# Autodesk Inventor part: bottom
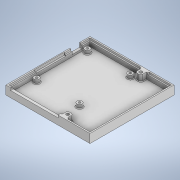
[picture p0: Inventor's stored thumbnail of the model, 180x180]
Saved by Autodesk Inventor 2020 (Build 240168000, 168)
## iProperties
Created: 2019-04
Part Number: bottom
Material: Generic
Document SubType Name: Modeling
Designer: Eli
Density: 1 g/cm^3
Appearance: Default
Author: Eli
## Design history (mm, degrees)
node "Blocks"
  sketch "raspberry pi"
    geometry: L1 (2.215, -51.877)-(7.411, -51.877); L2 (7.411, -51.877)-(7.411, -54.533); L3 (7.411, -54.533)-(2.215, -54.533); L4 (2.215, -54.533)-(2.215, -51.877); L5 (0, -50.5)-(-2.6, -50.5); L6 (-2.6, -50.5)-(-2.6, -56.5); L7 (-2.6, -56.5)-(0, -56.5); L8 (0, -56.5)-(0, -50.5); L9 (3, 0)-(53, 0); L10 (56, -3)-(56, -82); L11 (53, -85)-(3, -85); L12 (0, -82)-(0, -3); L13 (18.25, -65.5)-(2.25, -65.5); L14 (2.25, -65.5)-(2.25, -86.8); L15 (2.25, -86.8)-(18.25, -86.8); L16 (18.25, -86.8)-(18.25, -65.5); L17 (3.243, -69.856)-(18.209, -69.856); L18 (18.209, -69.856)-(18.209, -72.956); L19 (18.209, -72.956)-(3.243, -72.956); L20 (3.243, -72.956)-(3.243, -69.856); L21 (21.5, -69.6)-(36.5, -69.6); L22 (36.5, -69.6)-(36.5, -86.8); L23 (36.5, -86.8)-(21.5, -86.8); L24 (21.5, -86.8)-(21.5, -69.6); L25 (26.529, -75.869)-(31.485, -75.869); L26 (31.485, -75.869)-(31.485, -77.946); L27 (31.485, -77.946)-(26.529, -77.946); L28 (26.529, -77.946)-(26.529, -75.869); L29 (39.5, -69.6)-(54.5, -69.6); L30 (54.5, -69.6)-(54.5, -86.8); L31 (54.5, -86.8)-(39.5, -86.8); L32 (39.5, -86.8)-(39.5, -69.6); L33 (43.612, -74.555)-(48.568, -74.555); L34 (48.568, -74.555)-(48.568, -74.374); L35 (48.568, -74.374)-(43.612, -74.374); L36 (43.612, -74.374)-(43.612, -74.555); L37 (3.243, -69.856)-(18.209, -69.856); L38 (18.209, -69.856)-(18.209, -72.956); L39 (18.209, -72.956)-(3.243, -72.956); L40 (3.243, -72.956)-(3.243, -69.856); L41 (-1.5, -10.6)-(-1.5, -14.6); L42 (-1.5, -14.6)-(4, -14.6); L43 (4, -14.6)-(4, -6.6); L44 (4, -6.6)-(-1.5, -6.6); L45 (-1.5, -10.6)-(-1.5, -6.6); L46 (5.743, -8.617)-(12.685, -8.617); L47 (12.685, -8.617)-(12.685, -10.674); L48 (12.685, -10.674)-(5.743, -10.674); L49 (5.743, -10.674)-(5.743, -8.617); L50 (-1.8, -32)-(-1.8, -24.5); L51 (-1.8, -24.5)-(8.7, -24.5); L52 (8.7, -24.5)-(8.7, -39.5); L53 (8.7, -39.5)-(-1.8, -39.5); L54 (-1.8, -32)-(-1.8, -39.5); L55 (5.716, -28.781)-(12.585, -28.781); L56 (12.585, -28.781)-(12.585, -30.781); L57 (12.585, -30.781)-(5.716, -30.781); L58 (5.716, -30.781)-(5.716, -28.781); C1 r 1.375 at (3.5, -3.5); C2 r 3 at (3.5, -3.5); C3 r 1.375 at (52.5, -3.5); C4 r 3 at (52.5, -3.5); C5 r 3 at (3.5, -61.5); C6 r 1.375 at (3.5, -61.5); C7 r 3 at (52.5, -61.5); C8 r 1.375 at (52.5, -61.5); C9 r 3 at (52.5, -61.5); C10 r 1.375 at (52.5, -61.5); C11 r 3 at (3.5, -61.5); C12 r 1.375 at (3.5, -61.5); C13 r 1.375 at (3.5, -3.5); C14 r 3 at (3.5, -3.5); A1 r 3 centre (3, -3) between (3, 0) and (0, -3); A2 r 3 centre (53, -3) between (56, -3) and (53, 0); A3 r 3 centre (53, -82) between (53, -85) and (56, -82); A4 r 3 centre (3, -82) between (0, -82) and (3, -85); 6 further points
    constraints: 60 end point, 18 centre point, 9 parallel, 8 point on circle, 8 tangent, 7 coincident, 7 perpendicular, 5 horizontal, 3 midpoint, 3 point on line, 2 equal radius, 14 other
    dimensions: "d14" = 58 distance of C13.centre C12.centre; "d16" = 6 diameter of C9; "d17" = 2.75 diameter of C10; "d29" = 56 distance between parallel lines of L12 L10; "d37" = 3.5 distance from line of L10 C3.centre; "d38" = 3.5 distance from line of L9 C3.centre; "d41" = 58 distance of C1.centre C6.centre; "d42" = 6 diameter of C7; "d43" = 2.75 diameter of C8; "d44" = 16 distance between parallel lines of L16 L14; "d45" = 21.3 distance between parallel lines of L13 L15; "d46" = 10.25 distance from line of L12 point (10.25, -83.2); "d47" = 1.8 distance between parallel lines of L11 L15; "d48" = 15 distance of L22.end L23.end; "d49" = 17.2 distance of L21.end L22.end; "d50" = 29 distance from line of L12 point (29, -86.8); "d51" = 15 distance of L30.end L31.end; "d52" = 47 distance from line of point (47, -86.8) L12; "d111" = 2.6 distance of L7.end L6.end; "d213" = 58 distance of C3.centre C10.centre; "d318" = 5.5 distance between parallel lines of L43 L41; "d319" = 8 distance between parallel lines of L42 L44; "d322" = 53.5 distance from line of L9 point (-2.6, -53.5); "d324" = 7.5 distance of L50.start L50.end; "d325" = 10.5 distance of L50.end L51.end; "d326" = 15 distance of L51.end L52.end
sketch "Raspberry pi 3B+ layout"
  geometry: 1 further point
  node "raspberry pi:1"
sketch "Sketch4"
  geometry: L1 (0, 0)-(90, 0); L2 (90, 0)-(90, -90); L3 (90, -90)-(0, -90); L4 (0, -90)-(0, 0); L5 (93, -93)-(93, 3); L6 (93, 3)-(-3, 3); L7 (-3, 3)-(-3, -93); L8 (-3, -93)-(93, -93)
  constraints: 16 end point, 4 parallel, 2 perpendicular, 1 horizontal, 3 other
  dimensions: "d153" = 90 distance between parallel lines of L3 L1; "d154" = 90 distance between parallel lines of L2 L4; "d155" = 3 distance between parallel lines of L2 L5
extrude "box" new body sketch "Sketch4" distance "d156" = 10; taper "d157" = 0 deg
sketch "Sketch13"
  geometry: L1 (90, 0)-(0, 0) reference; L2 (0, 0)-(0, 90) reference; C1 r 3 at (4.5, 24.5); C2 r 3 at (53.5, 24.5); C3 r 3 at (53.5, 82.5); C4 r 3 at (4.5, 82.5)
  constraints: 4 centre point, 6 other
  dimensions: "d239" = 1 dimension on L1; "d241" = 1 dimension on L2
extrude "legs for the RP" join sketch "Sketch13" distance "d242" = 4.2; taper "d243" = 0 deg
sketch "Sketch35"
  geometry: C1 r 3 at (0, 0) reference; C2 r 3 at (0, -58) reference; C3 r 3 at (-49, -58) reference; C4 r 3 at (-49, 0) reference; 5 further points
  constraints: 4 coincident
hole "holes for the RP" sketch "Sketch35" at (0, 0), (0, -58), (-49, -58), (-49, 0) diameter "d411" = 2.5; stored, may be unused: countersink angle "d415" = 90 deg, drill point angle "d417" = 0 deg; dims "d412" = 6, "d413" = 4, "d414" = 2, "d416" = 6.5
sketch "Sketch23"
  geometry: L1 (-6.1, 5)-(-6.1, 11); L2 (-6.4, 5)-(-6.4, 11); L3 (-4.5, 65.5)-(-4.5, -24.5) reference; L4 (-4.5, 5)-(-6.1, 5); L5 (-4.5, 4)-(-7.1, 4); L6 (-4.5, 37)-(-5.3, 37); L7 (-4.5, 38)-(-5.3, 38); L8 (-4.5, 4)-(-6.4, 4); L9 (-6.4, 4)-(-6.4, 38); L10 (-6.4, 38)-(-4.5, 38); L11 (-4.5, 4)-(-4.5, 38); C1 r 3 at (49, 58) reference; C2 r 3 at (49, 0) reference; C3 r 1.25 at (49, 0) reference; 3 further points
  constraints: 20 end point, 3 point on line, 2 collinear, 2 parallel, 2 perpendicular, 2 vertical, 5 other
  dimensions: "d328" = 0 dimension on C2.centre; "d329" = 0 dimension on C3.centre; "d330" = 0.3 distance between parallel lines of L1 L2; "d331" = 1 distance between parallel lines of L4 L5; "d332" = 1 distance between parallel lines of L6 L7
extrude "Space for the HDMI and AUX" cut sketch "Sketch23" distance "d333" = 10; taper "d334" = 0 deg
sketch "Sketch16"
  geometry: L1 (-2.25, -28.375)-(-2.25, -23.966); L2 (52, -28.375)-(52, -23.5); L3 (52, -28.375)-(-2.25, -28.375); L4 (52, -23.5)-(-2.25, -23.5); L5 (-2.25, -23.5)-(-2.25, -23.966); C1 r 1.25 at (49, 0) reference; C2 r 3 at (49, 0) reference; 1 further point
  constraints: 10 end point, 2 perpendicular, 2 vertical
extrude "Hole for the USB and network" cut sketch "Sketch16" distance "d269" = 18.2; taper "d270" = 0 deg
sketch "Sketch17"
  geometry: L1 (-6, 45.9)-(-4.5, 45.9); L2 (-4.5, 55.9)-(-6, 55.9); L3 (-4.5, 65.5)-(-4.5, -24.5) reference; L4 (-4.5, 45.9)-(-9.232, 45.9); L5 (-9.232, 45.9)-(-9.232, 55.9); L6 (-9.232, 55.9)-(-4.5, 55.9); L7 (-4.5, 45.9)-(-4.5, 55.9); C1 r 3 at (49, 58) reference; 3 further points
  constraints: 12 end point, 2 point on line, 1 collinear, 1 horizontal, 1 parallel, 1 perpendicular
extrude "Hole for the power input" cut sketch "Sketch17" distance "d275" = 2.8; taper "d276" = 0 deg; dims "d391" = 2, "d392" = 0
sketch "Sketch19"
  geometry: L1 (-93, 93)-(-93, -3) reference; L2 (-93, -3)-(-87.75, -3) reference; L3 (-93, 93)-(-93, 80.4) reference; L4 (3, 93)-(-93, 93) reference; L5 (3, -3)-(3, 93) reference; L6 (-33.5, -3)-(3, -3) reference; L7 (-91.5, 91.5)-(1.5, 91.5); L8 (1.5, 91.5)-(1.5, -1.5); L9 (1.5, -1.5)-(-24, -1.5); L10 (-91.4, -1.5)-(-87.75, -1.488); L11 (-90, 28.5)-(-91.9, 28.5) reference; L12 (-91.5, 28.5)-(-90, 28.5); L13 (-90, 28.5)-(-90, 0); L14 (-90, 0)-(-87.75, 0); L15 (-87.75, 0)-(-87.75, -1.488); L16 (-90, 56.891)-(-90, 57.391) reference; L17 (-90, 80.4)-(-90, 90); L18 (0, 90)-(0, 0) reference; L19 (0, 90)-(0, 0); L20 (-33.5, -3)-(-33.5, 0) reference; L21 (-33.5, 0)-(-33.5, -1.5); L22 (-91.4, -1.5)-(-91.4, 28.5); L23 (-90, 62.5)-(-91.9, 62.5) reference; L24 (-91.467, 62.5)-(-90, 62.5); L25 (-90, 62.5)-(-90, 70.4) reference; L26 (-90, 62.5)-(-90, 70.4); L27 (-90, 70.4)-(-91.482, 70.4); L28 (-90, 70.4)-(-93, 70.4) reference; L29 (-91.9, 28.5)-(-91.9, 62.5) reference; L30 (-91.5, 91.5)-(-91.5, 80.4); L31 (-93, 80.4)-(-90, 80.4) reference; L32 (-93, 80.4)-(-90, 80.4) reference; L33 (-91.4, 25.893)-(-91.5, 80.4); L34 (-91.467, 62.5)-(-91.482, 70.4); L35 (3, 93)-(-93, 93) reference; L36 (-90, 0)-(0, 0) reference; L37 (0, 0)-(-24, 0); L38 (-33.5, -3)-(-33.5, -1.5); L39 (-33.5, 0)-(-33.5, 93); L40 (-33.5, 91.5)-(-33.5, 90); L41 (-90, 90)-(0, 90) reference; L42 (-90, 90)-(-33.5, 90); L43 (-24, 90)-(0, 90); L44 (-32, 93)-(-32, 0); L45 (-32, 0)-(-32, -1.5); L46 (-32, -1.5)-(-32, -3); L47 (-24, 93)-(-24, 0); L48 (-24, 0)-(-24, -1.5); L49 (-24, -1.5)-(-24, -3); L50 (-24, -1.5)-(-24, 0); L51 (0, 0)-(-33.5, 0) reference; L52 (0, 90)-(-90, 90) reference; L53 (-24, 90)-(-24, 91.5); 11 further points
  constraints: 64 end point, 16 point on line, 8 perpendicular, 3 collinear, 3 vertical, 1 horizontal, 1 midpoint, 6 other
  dimensions: "d280" = 1.5 distance between parallel lines of L4 L7; "d362" = 1.5 distance between parallel lines of L39 L44; "d363" = 8 distance between parallel lines of L44 L47
extrude "Railing for the second part" cut sketch "Sketch19" distance "d282" = 2; taper "d283" = 0 deg
sketch "Sketch29"
  geometry: L1 (-90, 0)-(0, 0) reference; L2 (-33.5, 0)-(-33.5, -3) reference; L3 (-24, -1.5)-(-24, 0) reference; L4 (-32, 0)-(-32, 90); L5 (0, 90)-(-90, 90) reference; L6 (-25.5, 0)-(-25.5, 90); L7 (-32, 0)-(-25.5, 0); L8 (-25.5, 0)-(-25.5, 6.5); L9 (-25.5, 6.5)-(-32, 6.5); L10 (-32, 6.5)-(-32, 0); L11 (-32, 90)-(-25.5, 90); L12 (-25.5, 90)-(-25.5, 83.5); L13 (-25.5, 83.5)-(-32, 83.5); L14 (-32, 83.5)-(-32, 90)
  constraints: 20 end point, 4 parallel, 3 point on line, 2 horizontal, 2 perpendicular, 2 vertical
  dimensions: "d364" = 1.5 distance from line of L2 L4.start; "d365" = 1.5 distance from line of L6.start L3; "d366" = 6.5 distance of L9.end L8.end; "d367" = 6.5 distance of L8.end L7.end; "d368" = 6.5 distance of L12.end L13.end; "d369" = 6.5 distance of L11.end L12.end
extrude "blocks to connect the top with" join sketch "Sketch29" stored distance "d370" = 4.5; taper "d371" = 0 deg
sketch "Sketch30"
  geometry: L1 (-32, -6.5)-(-32, 0) reference; L2 (-24, 0)-(-25.5, 0) reference; L3 (-32, -6.5)-(-25.5, 0); L4 (-25.5, 0)-(-25.5, -6.5) reference; L5 (-32, 0)-(-33.5, 0) reference; L6 (-25.5, -6.5)-(-32, 0); L7 (-32, -83.5)-(-25.5, -83.5) reference; L8 (-25.5, -83.5)-(-25.5, -90) reference; L9 (-32, -83.5)-(-25.5, -90); L10 (-32, -90)-(-90, -90) reference; L11 (-32, -90)-(-25.5, -83.5); 3 further points
  constraints: 8 end point, 2 midpoint
hole "holes to connect to the top" sketch "Sketch30" at (-28.75, -86.75), (-28.75, -3.25) diameter "d372" = 3.4; stored, may be unused: countersink angle "d376" = 50 deg, drill point angle "d378" = 118 deg; dims "d373" = 6, "d374" = 5.4, "d375" = 5, "d377" = 8
fillet "Fillet for blocks on the inside" dims "d379" = 2.5
node "fixed size for power input"
fillet "Fillet5" dims "d418" = 0.8
body "Solid1"
feature "shell" dims "d158" = 3
node "raspberry pi:2" dims "d239" = 1, "d241" = 1
node "raspberry pi:3" dims "d328" = 0, "d329" = 0, "d330" = 0.3, "d331" = 1, "d332" = 1
move_body "Move5" dims "d407" = -0.7
move_body "Move6" dims "d410" = -0.7
other parameters: "d344" = 1.5, "d405" = 0, "d406" = 0, "d408" = 0, "d409" = 0
